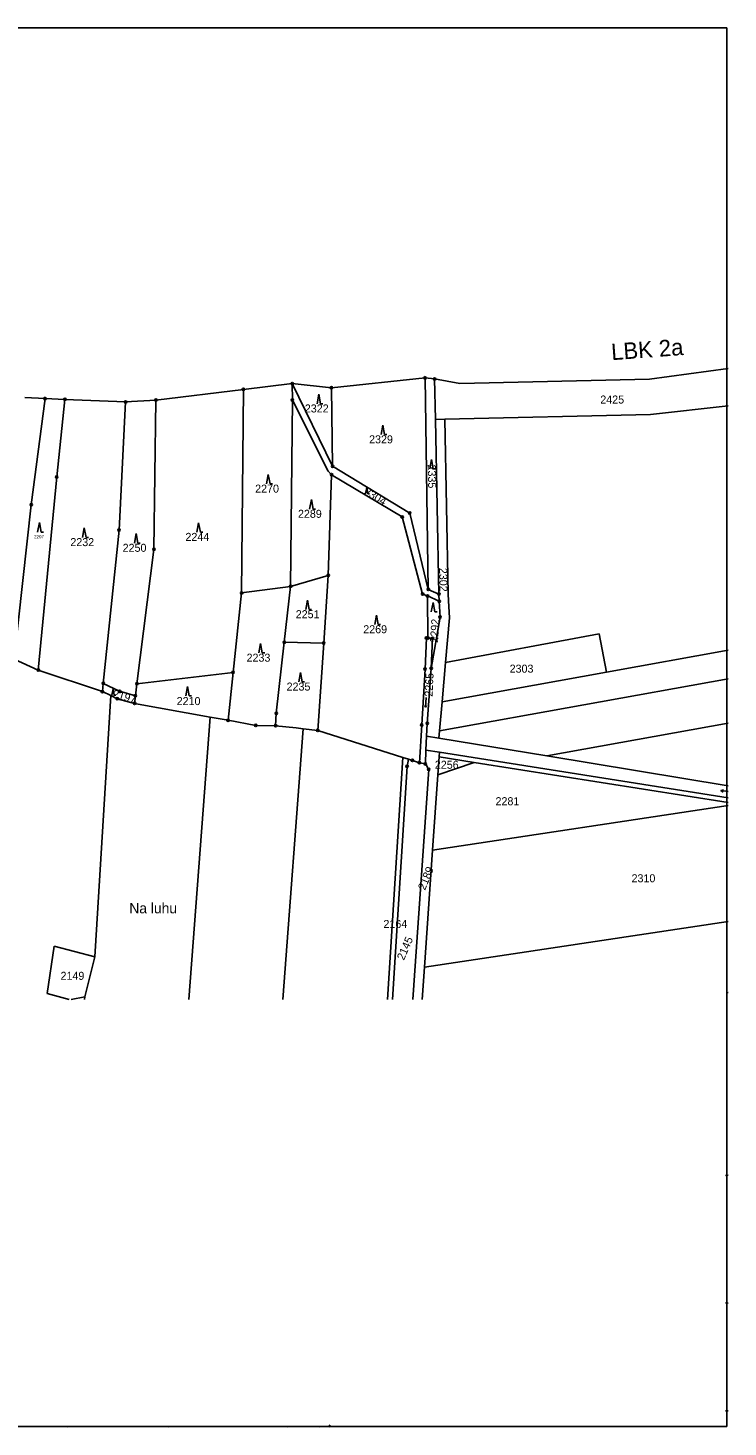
# Model space of a CAD drawing. Extents: x -566461 to -565198, y -1096301 to -1095707.
# Drawn here: x -565495 to -565198, y -1096301 to -1095707 of the extents above; entities that cross this region are included whole.
import ezdxf

# ---------------------------------------------------------------- set-up
doc = ezdxf.new("R2010")
doc.units = 0
for name, color, linetype in [('Vrstva 1', 7, 'Continuous'), ('Vrstva 13', 7, 'Continuous'), ('Vrstva 15', 7, 'Continuous'), ('Vrstva 18', 7, 'Continuous'), ('Vrstva 24', 7, 'Continuous'), ('Vrstva 25', 7, 'Continuous'), ('Vrstva 63', 7, 'Continuous')]:
    doc.layers.add(name, color=color, linetype=linetype)

msp = doc.modelspace()

# ---------------------------------------------------------------- linework, layer by layer
at = {"layer": 'Vrstva 1'}
for p, q in [((-565325.3, -1095945.49), (-565326.62, -1095855.64)), ((-565322.28, -1095873.28), (-565322.62, -1095856.13)), ((-565404.57, -1095947.01), (-565403.8, -1095860.58)), ((-565383.09, -1095858.05), (-565383.02, -1095865.11)), ((-565383.09, -1095858.05), (-565365.95, -1095893.19)), ((-565365.95, -1095893.19), (-565366.41, -1095859.87)), ((-565493.97, -1095909.58), (-565488.06, -1095864.42)), ((-565483.13, -1095897.74), (-565479.68, -1095864.78)), ((-565456.67, -1095920.29), (-565453.87, -1095865.89)), ((-565441.83, -1095928.52), (-565440.98, -1095865.12)), ((-565383.02, -1095865.11), (-565383.78, -1095944.21)), ((-565383.02, -1095865.11), (-565367.82, -1095895.28)), ((-565197.94, -1095867.5), (-565230.93, -1095871.19)), ((-565318.28, -1095873.19), (-565322.28, -1095873.28)), ((-565322.28, -1095873.28), (-565320.79, -1095947.48)), ((-565318.28, -1095873.19), (-565230.93, -1095871.19)), ((-565316.79, -1095947.33), (-565318.28, -1095873.19)), ((-565365.95, -1095893.19), (-565333.17, -1095913.11)), ((-565483.13, -1095897.74), (-565490.98, -1095979.78)), ((-565366.39, -1095896.77), (-565367.82, -1095895.28)), ((-565367.79, -1095939.56), (-565366.39, -1095896.77)), ((-565336.37, -1095914.75), (-565366.39, -1095896.77)), ((-565493.97, -1095909.58), (-565501.17, -1095975.14)), ((-565336.37, -1095914.75), (-565327.73, -1095947.49)), ((-565325.3, -1095945.49), (-565333.17, -1095913.11)), ((-565463.34, -1095985.45), (-565456.67, -1095920.29)), ((-565441.83, -1095928.52), (-565449.03, -1095985.59)), ((-565367.79, -1095939.56), (-565383.78, -1095944.21)), ((-565367.79, -1095939.56), (-565369.72, -1095968.34)), ((-565404.57, -1095947.01), (-565383.78, -1095944.21)), ((-565383.78, -1095944.21), (-565386.46, -1095967.93)), ((-565325.3, -1095945.49), (-565320.79, -1095947.48)), ((-565404.57, -1095947.01), (-565408.18, -1095980.8)), ((-565325.61, -1095948.29), (-565327.73, -1095947.49)), ((-565325.61, -1095948.29), (-565325.42, -1095966.15)), ((-565320.63, -1095950.54), (-565325.61, -1095948.29)), ((-565320.79, -1095947.48), (-565320.63, -1095950.54)), ((-565320.63, -1095950.54), (-565320.28, -1095957.29)), ((-565316.63, -1095950.33), (-565316.79, -1095947.33)), ((-565316.26, -1095957.53), (-565316.63, -1095950.33)), ((-565320.28, -1095957.29), (-565324.05, -1095979.07)), ((-565317.95, -1095976.6), (-565316.26, -1095957.53)), ((-565252.64, -1095964.38), (-565317.95, -1095976.6)), ((-565252.64, -1095964.38), (-565249.5, -1095980.6)), ((-565386.46, -1095967.93), (-565389.86, -1095998.08)), ((-565369.72, -1095968.34), (-565386.46, -1095967.93)), ((-565369.72, -1095968.34), (-565372.21, -1096005.43)), ((-565326.08, -1095966.11), (-565326.66, -1095979.34)), ((-565326.08, -1095966.11), (-565325.42, -1095966.15)), ((-565323.47, -1095966.28), (-565325.42, -1095966.15)), ((-565324.05, -1095979.07), (-565323.47, -1095966.28)), ((-565490.98, -1095979.78), (-565501.17, -1095975.14)), ((-565249.5, -1095980.6), (-565197.94, -1095971.32)), ((-565463.69, -1095988.88), (-565490.98, -1095979.78)), ((-565449.03, -1095985.59), (-565408.18, -1095980.8)), ((-565410.35, -1096001.11), (-565408.18, -1095980.8)), ((-565326.66, -1095979.34), (-565328.04, -1096003.07)), ((-565324.05, -1095979.07), (-565325.74, -1096002.43)), ((-565319.41, -1095993.25), (-565317.95, -1095976.6)), ((-565249.5, -1095980.6), (-565319.41, -1095993.25)), ((-565463.34, -1095985.45), (-565463.69, -1095988.88)), ((-565456.43, -1095988.79), (-565463.34, -1095985.45)), ((-565449.03, -1095985.59), (-565449.67, -1095990.68)), ((-565320.5, -1096005.65), (-565197.94, -1095983.53)), ((-565460.14, -1095990.61), (-565466.93, -1096101.52)), ((-565460.14, -1095990.61), (-565463.69, -1095988.88)), ((-565460.14, -1095990.61), (-565457.43, -1095991.93)), ((-565450.08, -1095993.9), (-565457.43, -1095991.93)), ((-565456.43, -1095988.79), (-565449.67, -1095990.68)), ((-565449.67, -1095990.68), (-565450.08, -1095993.9)), ((-565450.08, -1095993.9), (-565417.9, -1095999.74)), ((-565320.5, -1096005.65), (-565319.41, -1095993.25)), ((-565427.07, -1096119.67), (-565417.9, -1095999.74)), ((-565417.9, -1095999.74), (-565410.35, -1096001.11)), ((-565389.86, -1095998.08), (-565390.13, -1096003.44)), ((-565410.35, -1096001.11), (-565398.57, -1096003.25)), ((-565390.13, -1096003.44), (-565398.57, -1096003.25)), ((-565381.38, -1096004.3), (-565390.13, -1096003.44)), ((-565378.38, -1096004.67), (-565387.09, -1096119.67)), ((-565378.38, -1096004.67), (-565381.38, -1096004.3)), ((-565372.21, -1096005.43), (-565378.38, -1096004.67)), ((-565336.02, -1096016.85), (-565372.21, -1096005.43)), ((-565329.05, -1096019.13), (-565328.04, -1096003.07)), ((-565325.74, -1096002.43), (-565325.98, -1096007.86)), ((-565320.77, -1096008.72), (-565320.5, -1096005.65)), ((-565274.95, -1096016.25), (-565197.94, -1096002.35)), ((-565325.98, -1096007.86), (-565326.25, -1096013.79)), ((-565320.77, -1096008.72), (-565325.98, -1096007.86)), ((-565274.95, -1096016.25), (-565320.77, -1096008.72)), ((-565342.55, -1096119.67), (-565336.02, -1096016.85)), ((-565333.74, -1096017.57), (-565336.02, -1096016.85)), ((-565333.74, -1096017.57), (-565334.25, -1096020.7)), ((-565332, -1096018.12), (-565333.74, -1096017.57)), ((-565326.25, -1096013.79), (-565326.51, -1096019.6)), ((-565320.57, -1096014.69), (-565326.25, -1096013.79)), ((-565321.24, -1096024.26), (-565320.71, -1096016.69)), ((-565320.71, -1096016.69), (-565320.57, -1096014.69)), ((-565305.78, -1096019.05), (-565320.71, -1096016.69)), ((-565320.57, -1096014.69), (-565197.94, -1096034.08)), ((-565197.94, -1096028.89), (-565274.95, -1096016.25)), ((-565334.25, -1096020.7), (-565340.54, -1096119.67)), ((-565329.05, -1096019.13), (-565332, -1096018.12)), ((-565331.88, -1096119.67), (-565325.09, -1096021.97)), ((-565326.51, -1096019.6), (-565329.05, -1096019.13)), ((-565325.09, -1096021.97), (-565326.51, -1096019.6)), ((-565305.78, -1096019.05), (-565321.24, -1096024.26)), ((-565197.94, -1096036.09), (-565305.78, -1096019.05)), ((-565323.47, -1096056.29), (-565321.24, -1096024.26)), ((-565323.47, -1096056.29), (-565197.94, -1096037.36)), ((-565326.92, -1096105.96), (-565323.47, -1096056.29)), ((-565326.92, -1096105.96), (-565197.94, -1096086.5)), ((-565487.2, -1096117.1), (-565484.15, -1096097.02)), ((-565466.93, -1096101.52), (-565484.15, -1096097.02)), ((-565471.2, -1096118.61), (-565466.93, -1096101.52)), ((-565327.87, -1096119.67), (-565326.92, -1096105.96)), ((-565487.2, -1096117.1), (-565477.84, -1096119.67)), ((-565476.94, -1096119.67), (-565471.2, -1096118.61)), ((-565471.2, -1096118.61), (-565471.33, -1096119.67)), ((-565197.94, -1096116.77), (-565198.38, -1096116.84)), ((-565197.94, -1096194.31), (-565199.03, -1096194.41)), ((-565199.03, -1096248.62), (-565197.94, -1096248.64)), ((-565197.94, -1096294.47), (-565199.03, -1096294.46)), ((-565478.56, -1096301.03), (-565478.67, -1096301.3)), ((-565435.95, -1096301.3), (-565435.85, -1096301.03)), ((-565385.21, -1096301.03), (-565385.32, -1096301.3)), ((-565383.07, -1096301.03), (-565383.17, -1096301.3)), ((-565371.86, -1096301.3), (-565371.75, -1096301.03)), ((-565367.17, -1096300.4), (-565367.54, -1096301.3)), ((-565367.54, -1096301.3), (-565367.43, -1096301.03))]:
    msp.add_line(p, q, dxfattribs=at)
at = {"layer": 'Vrstva 13'}
for p, q in [((-565231.27, -1095856.19), (-565197.94, -1095851.65)), ((-565366.41, -1095859.87), (-565326.62, -1095855.64)), ((-565326.62, -1095855.64), (-565322.62, -1095856.13)), ((-565322.62, -1095856.13), (-565311.82, -1095858.04)), ((-565311.82, -1095858.04), (-565231.27, -1095856.19)), ((-565440.98, -1095865.12), (-565403.8, -1095860.58)), ((-565403.8, -1095860.58), (-565383.09, -1095858.05)), ((-565383.09, -1095858.05), (-565366.41, -1095859.87)), ((-565496.71, -1095864.05), (-565488.06, -1095864.42)), ((-565488.06, -1095864.42), (-565479.68, -1095864.78)), ((-565479.68, -1095864.78), (-565453.87, -1095865.89)), ((-565453.87, -1095865.89), (-565440.98, -1095865.12))]:
    msp.add_line(p, q, dxfattribs=at)
at = {"layer": 'Vrstva 24'}
for centre, radius in [((-565383.09, -1095858.05), 0.5), ((-565326.62, -1095855.64), 0.5), ((-565326.62, -1095855.64), 0.0327), ((-565322.62, -1095856.13), 0.5), ((-565322.62, -1095856.13), 0.0327), ((-565403.8, -1095860.58), 0.5), ((-565403.8, -1095860.58), 0.0327), ((-565383.09, -1095858.05), 0.0327), ((-565366.41, -1095859.87), 0.5), ((-565366.41, -1095859.87), 0.0327), ((-565488.06, -1095864.42), 0.5), ((-565488.06, -1095864.42), 0.0327), ((-565479.68, -1095864.78), 0.5), ((-565479.68, -1095864.78), 0.0327), ((-565453.87, -1095865.89), 0.5), ((-565453.87, -1095865.89), 0.0327), ((-565440.98, -1095865.12), 0.5), ((-565440.98, -1095865.12), 0.0327), ((-565383.02, -1095865.11), 0.5), ((-565383.02, -1095865.11), 0.0327), ((-565365.95, -1095893.19), 0.5), ((-565365.95, -1095893.19), 0.0327), ((-565483.13, -1095897.74), 0.5), ((-565483.13, -1095897.74), 0.0327), ((-565366.39, -1095896.77), 0.5), ((-565366.39, -1095896.77), 0.0327), ((-565493.97, -1095909.58), 0.5), ((-565493.97, -1095909.58), 0.0327), ((-565336.37, -1095914.75), 0.5), ((-565336.37, -1095914.75), 0.0327), ((-565333.17, -1095913.11), 0.5), ((-565333.17, -1095913.11), 0.0327), ((-565456.67, -1095920.29), 0.5), ((-565456.67, -1095920.29), 0.0327), ((-565441.83, -1095928.52), 0.5), ((-565441.83, -1095928.52), 0.0327), ((-565367.79, -1095939.56), 0.5), ((-565367.79, -1095939.56), 0.0327), ((-565404.57, -1095947.01), 0.5), ((-565383.78, -1095944.21), 0.5), ((-565383.78, -1095944.21), 0.0327), ((-565325.3, -1095945.49), 0.5), ((-565325.3, -1095945.49), 0.0327), ((-565404.57, -1095947.01), 0.0327), ((-565327.73, -1095947.49), 0.5), ((-565327.73, -1095947.49), 0.0327), ((-565325.61, -1095948.29), 0.5), ((-565325.61, -1095948.29), 0.0327), ((-565320.79, -1095947.48), 0.5), ((-565320.63, -1095950.54), 0.5), ((-565320.79, -1095947.48), 0.0327), ((-565320.63, -1095950.54), 0.0327), ((-565320.28, -1095957.29), 0.5), ((-565320.28, -1095957.29), 0.0327), ((-565386.46, -1095967.93), 0.5), ((-565386.46, -1095967.93), 0.0327), ((-565369.72, -1095968.34), 0.5), ((-565369.72, -1095968.34), 0.0327), ((-565326.08, -1095966.11), 0.5), ((-565326.08, -1095966.11), 0.0327), ((-565325.42, -1095966.15), 0.5), ((-565325.42, -1095966.15), 0.0327), ((-565323.47, -1095966.28), 0.5), ((-565323.47, -1095966.28), 0.0327), ((-565490.98, -1095979.78), 0.5), ((-565490.98, -1095979.78), 0.0327), ((-565408.18, -1095980.8), 0.5), ((-565408.18, -1095980.8), 0.0327), ((-565326.66, -1095979.34), 0.5), ((-565326.66, -1095979.34), 0.0327), ((-565324.05, -1095979.07), 0.5), ((-565324.05, -1095979.07), 0.0327), ((-565463.69, -1095988.88), 0.5), ((-565463.34, -1095985.45), 0.5), ((-565463.34, -1095985.45), 0.0327), ((-565456.43, -1095988.79), 0.5), ((-565449.03, -1095985.59), 0.5), ((-565449.03, -1095985.59), 0.0327), ((-565463.69, -1095988.88), 0.0327), ((-565457.43, -1095991.93), 0.5), ((-565457.43, -1095991.93), 0.0327), ((-565456.43, -1095988.79), 0.0327), ((-565450.08, -1095993.9), 0.5), ((-565449.67, -1095990.68), 0.5), ((-565450.08, -1095993.9), 0.0327), ((-565449.67, -1095990.68), 0.0327), ((-565389.86, -1095998.08), 0.5), ((-565389.86, -1095998.08), 0.0327), ((-565410.35, -1096001.11), 0.5), ((-565410.35, -1096001.11), 0.0327), ((-565398.57, -1096003.25), 0.5), ((-565398.57, -1096003.25), 0.0327), ((-565390.13, -1096003.44), 0.5), ((-565390.13, -1096003.44), 0.0327), ((-565372.21, -1096005.43), 0.5), ((-565372.21, -1096005.43), 0.0327), ((-565328.04, -1096003.07), 0.5), ((-565328.04, -1096003.07), 0.0327), ((-565325.74, -1096002.43), 0.5), ((-565325.74, -1096002.43), 0.0327), ((-565332, -1096018.12), 0.5), ((-565332, -1096018.12), 0.0327), ((-565334.25, -1096020.7), 0.5), ((-565334.25, -1096020.7), 0.0327), ((-565329.05, -1096019.13), 0.5), ((-565329.05, -1096019.13), 0.0327), ((-565326.51, -1096019.6), 0.5), ((-565326.51, -1096019.6), 0.0327), ((-565325.09, -1096021.97), 0.5), ((-565325.09, -1096021.97), 0.0327)]:
    msp.add_circle(centre, radius, dxfattribs=at)
at = {"layer": 'Vrstva 25'}
for p, q in [((-565371.79, -1095862.63), (-565372.53, -1095866.63)), ((-565371.79, -1095862.63), (-565371.06, -1095866.63)), ((-565371.06, -1095866.63), (-565370.06, -1095866.63)), ((-565344.62, -1095875.75), (-565345.35, -1095879.75)), ((-565344.62, -1095875.75), (-565343.89, -1095879.75)), ((-565343.89, -1095879.75), (-565342.89, -1095879.75)), ((-565323.9, -1095890.3), (-565324.64, -1095894.3)), ((-565323.9, -1095890.3), (-565323.17, -1095894.3)), ((-565393.23, -1095896.68), (-565393.96, -1095900.68)), ((-565393.23, -1095896.68), (-565392.5, -1095900.68)), ((-565323.17, -1095894.3), (-565322.17, -1095894.3)), ((-565392.5, -1095900.68), (-565391.5, -1095900.68)), ((-565351.45, -1095902.21), (-565351.94, -1095904.89)), ((-565351.45, -1095902.21), (-565350.95, -1095904.89)), ((-565350.95, -1095904.89), (-565350.28, -1095904.89)), ((-565374.96, -1095907.38), (-565375.7, -1095911.38)), ((-565374.96, -1095907.38), (-565374.23, -1095911.38)), ((-565374.23, -1095911.38), (-565373.23, -1095911.38)), ((-565490.5, -1095917.13), (-565491.23, -1095921.13)), ((-565490.5, -1095917.13), (-565489.77, -1095921.13)), ((-565489.77, -1095921.13), (-565488.77, -1095921.13)), ((-565471.4, -1095919.41), (-565472.14, -1095923.41)), ((-565471.4, -1095919.41), (-565470.67, -1095923.41)), ((-565449.36, -1095921.82), (-565450.09, -1095925.82)), ((-565449.36, -1095921.82), (-565448.63, -1095925.82)), ((-565422.83, -1095917.19), (-565423.57, -1095921.19)), ((-565422.83, -1095917.19), (-565422.1, -1095921.19)), ((-565422.1, -1095921.19), (-565421.1, -1095921.19)), ((-565470.67, -1095923.41), (-565469.67, -1095923.41)), ((-565448.63, -1095925.82), (-565447.63, -1095925.82)), ((-565376.57, -1095950.03), (-565377.31, -1095954.03)), ((-565376.57, -1095950.03), (-565375.84, -1095954.03)), ((-565323.27, -1095951), (-565324.01, -1095955)), ((-565323.27, -1095951), (-565322.54, -1095955)), ((-565375.84, -1095954.03), (-565374.84, -1095954.03)), ((-565347.28, -1095956.42), (-565348.02, -1095960.42)), ((-565347.28, -1095956.42), (-565346.55, -1095960.42)), ((-565322.54, -1095955), (-565321.54, -1095955)), ((-565346.55, -1095960.42), (-565345.55, -1095960.42)), ((-565396.51, -1095968.5), (-565397.24, -1095972.5)), ((-565396.51, -1095968.5), (-565395.78, -1095972.5)), ((-565395.78, -1095972.5), (-565394.78, -1095972.5)), ((-565379.58, -1095980.77), (-565380.32, -1095984.77)), ((-565379.58, -1095980.77), (-565378.85, -1095984.77)), ((-565459.18, -1095987.74), (-565459.67, -1095990.42)), ((-565459.18, -1095987.74), (-565458.68, -1095990.42)), ((-565427.58, -1095986.68), (-565428.32, -1095990.68)), ((-565427.58, -1095986.68), (-565426.85, -1095990.68)), ((-565378.85, -1095984.77), (-565377.85, -1095984.77)), ((-565458.68, -1095990.42), (-565458.01, -1095990.42)), ((-565426.85, -1095990.68), (-565425.85, -1095990.68)), ((-565326.2, -1095991.44), (-565326.4, -1095995.46)), ((-565197.94, -1096031.4), (-565200.94, -1096030.92))]:
    msp.add_line(p, q, dxfattribs=at)
for points in [[(-565326.03, -1095994.8), (-565326.4, -1095995.46), (-565326.7, -1095994.77)], [(-565200.03, -1096031.57), (-565200.94, -1096030.92), (-565199.88, -1096030.58)]]:
    msp.add_lwpolyline(points, dxfattribs=at)
at = {"layer": 'Vrstva 63'}
for p, q in [((-566458.38, -1095707.03), (-565198.38, -1095707.03)), ((-565198.38, -1095707.03), (-565198.38, -1096301.03)), ((-565198.38, -1096301.03), (-566458.38, -1096301.03))]:
    msp.add_line(p, q, dxfattribs=at)

# ---------------------------------------------------------------- texts
at = {"layer": 'Vrstva 1'}
msp.add_text('LBK 2a', height=7, rotation=4.15955, dxfattribs=at).set_placement((-565247.32, -1095848.16))
at = {"layer": 'Vrstva 15'}
msp.add_text('Na luhu', height=4.4, dxfattribs=at).set_placement((-565452.29, -1096083.11))
at = {"layer": 'Vrstva 18'}
for s, height, p in [('2425', 3.4, (-565252.2, -1095866.55)), ('2322', 3.4, (-565377.73, -1095870.34)), ('2329', 3.4, (-565350.42, -1095883.46)), ('2270', 3.4, (-565398.82, -1095904.39)), ('2289', 3.4, (-565380.64, -1095915.09)), ('2207', 1.36, (-565492.76, -1095923.82)), ('2244', 3.4, (-565428.45, -1095924.9)), ('2232', 3.4, (-565477.34, -1095927.12)), ('2250', 3.4, (-565455.13, -1095929.53)), ('2251', 3.4, (-565381.59, -1095957.74)), ('2269', 3.4, (-565352.9, -1095964.13)), ('2233', 3.4, (-565402.48, -1095976.21)), ('2303', 3.4, (-565290.72, -1095980.87)), ('2235', 3.4, (-565385.47, -1095988.48)), ('2210', 3.4, (-565432.18, -1095994.64)), ('2256', 3.4, (-565322.49, -1096021.69)), ('2281', 3.4, (-565296.71, -1096037.18)), ('2310', 3.4, (-565238.92, -1096069.91)), ('2164', 3.4, (-565344.33, -1096089.32)), ('2149', 3.4, (-565481.51, -1096111.34))]:
    msp.add_text(s, height=height, dxfattribs=at).set_placement(p)
for s, rotation, p in [('2335', 270.9, (-565325.48, -1095892.49)), ('2304', 329.4, (-565353.01, -1095904.85)), ('2302', 270.9, (-565320.63, -1095936.38)), ('2292', 86.4, (-565321.18, -1095968.24)), ('2265', 87.3, (-565323.49, -1095991.15)), ('2197', 343.8, (-565459.68, -1095991.25)), ('2189', 67.5, (-565326.67, -1096073.51)), ('2145', 66.6, (-565335.64, -1096103.26))]:
    msp.add_text(s, height=3.4, rotation=rotation, dxfattribs=at).set_placement(p)

doc.saveas('drawing.dxf')
